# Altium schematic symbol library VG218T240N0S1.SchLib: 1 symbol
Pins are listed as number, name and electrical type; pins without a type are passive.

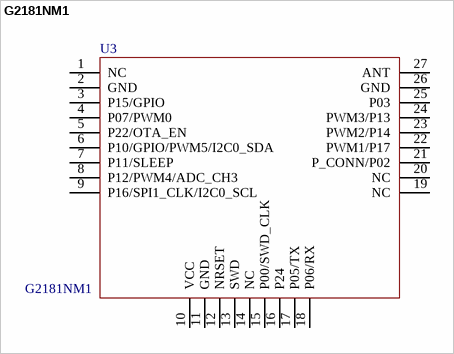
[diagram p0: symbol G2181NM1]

## G2181NM1
designator U3
footprint G2181NM1_SMD
pins: 1 NC, 2 GND, 3 P15/GPIO, 4 P07/PWM0, 5 P22/OTA_EN, 6 P10/GPIO/PWM5/I2C0_SDA, 7 P11/SLEEP, 8 P12/PWM4/ADC_CH3, 9 P16/SPI1_CLK/I2C0_SCL, 10 VCC, 11 GND, 12 NRSET, 13 SWD, 14 NC, 15 P00/SWD_CLK, 16 P24, 17 P05/TX, 18 P06/RX, 19 NC, 20 NC, 21 P_CONN/P02, 22 PWM1/P17, 23 PWM2/P14, 24 PWM3/P13, 25 P03, 26 GND, 27 ANT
